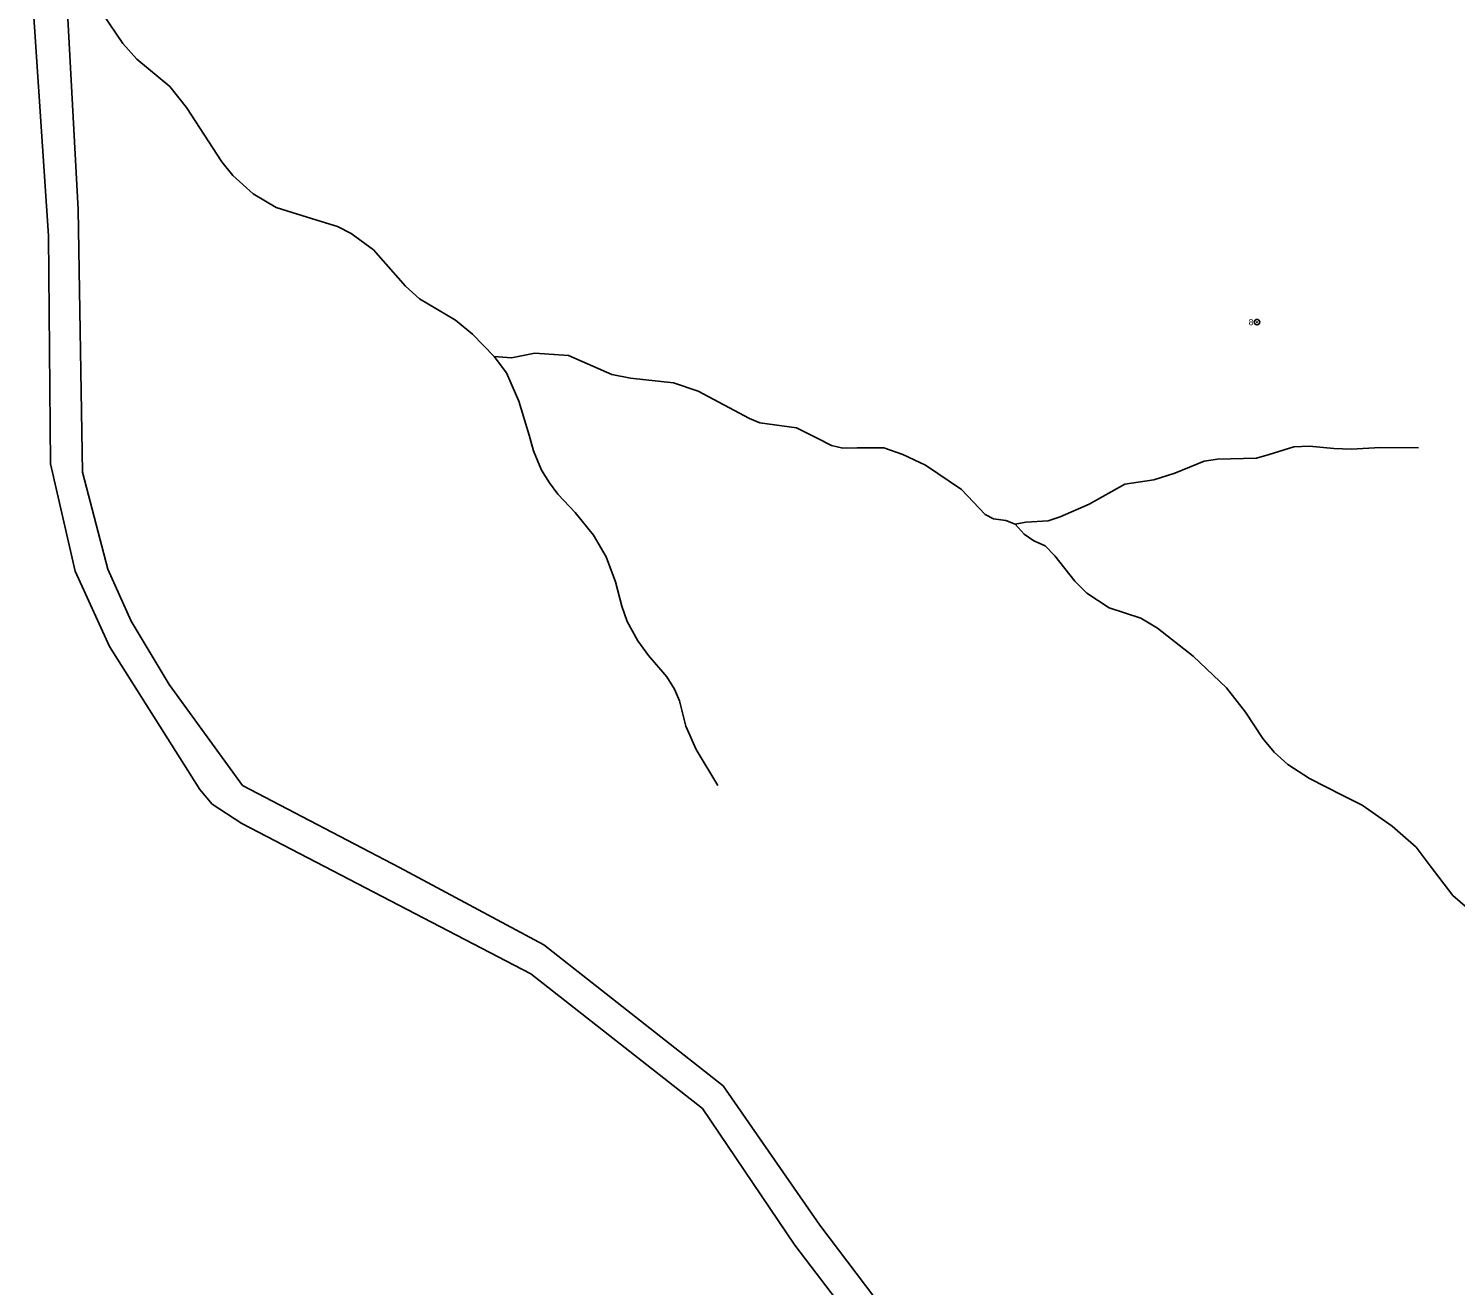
# Model space of a CAD drawing. Extents: x -546762 to -540209, y -1046851 to -1035694.
# Drawn here: x -543936.4 to -543546.4, y -1043117.1 to -1042773.8 of the extents above; entities that cross this region are included whole.
import ezdxf

# ---------------------------------------------------------------- set-up
doc = ezdxf.new("R2010")
doc.units = 0
for name, color, linetype in [('Vrstva 1', 7, 'Continuous'), ('Vrstva 17', 7, 'Continuous'), ('Vrstva 24', 7, 'Continuous'), ('Vrstva 4', 7, 'Continuous')]:
    doc.layers.add(name, color=color, linetype=linetype)

msp = doc.modelspace()

# ---------------------------------------------------------------- linework, layer by layer
at = {"layer": 'Vrstva 1'}
for points in [[(-543930.94, -1042830.38), (-543936.37, -1042748.84)], [(-543922.81, -1042823.23), (-543926.46, -1042755.84)], [(-543921.61, -1042894.96), (-543922.81, -1042823.23)], [(-543930.35, -1042892.69), (-543930.94, -1042830.38)], [(-543923.63, -1042921.97), (-543930.35, -1042892.69)], [(-543914.71, -1042921.46), (-543921.61, -1042894.96)], [(-543908.32, -1042935.68), (-543914.71, -1042921.46)], [(-543914.29, -1042942.58), (-543923.63, -1042921.97)], [(-543897.98, -1042952.93), (-543908.32, -1042935.68)], [(-543889.56, -1042981.62), (-543914.29, -1042942.58)], [(-543877.87, -1042980.57), (-543897.98, -1042952.93)], [(-543886.19, -1042985.65), (-543889.56, -1042981.62)], [(-543834.97, -1043002.95), (-543877.87, -1042980.57)], [(-543878.08, -1042990.91), (-543886.19, -1042985.65)], [(-543799.14, -1043031.96), (-543878.08, -1042990.91)], [(-543795.53, -1043024.03), (-543834.97, -1043002.95)], [(-543746.54, -1043062.55), (-543795.53, -1043024.03)], [(-543752.17, -1043068.79), (-543799.14, -1043031.96)], [(-543720.13, -1043100.6), (-543746.54, -1043062.55)], [(-543726.97, -1043106.1), (-543752.17, -1043068.79)], [(-543695.18, -1043133.63), (-543720.13, -1043100.6)], [(-543699.83, -1043141.7), (-543726.97, -1043106.1)]]:
    msp.add_lwpolyline(points, dxfattribs=at)
at = {"layer": 'Vrstva 24'}
for radius in [0.75, 0.1]:
    msp.add_circle((-543600.66, -1042853.96), radius, dxfattribs=at)
at = {"layer": 'Vrstva 4'}
for points in [[(-543916.14, -1042769.65), (-543910.63, -1042777.9)], [(-543910.63, -1042777.9), (-543906.82, -1042782.14)], [(-543906.82, -1042782.14), (-543897.79, -1042789.63)], [(-543897.79, -1042789.63), (-543893.18, -1042795.32)], [(-543893.18, -1042795.32), (-543883.58, -1042810.14)], [(-543883.58, -1042810.14), (-543880.52, -1042813.96)], [(-543880.52, -1042813.96), (-543875.01, -1042818.96)], [(-543875.01, -1042818.96), (-543868.68, -1042822.66)], [(-543868.68, -1042822.66), (-543858.78, -1042825.72)], [(-543858.78, -1042825.72), (-543851.98, -1042827.81)], [(-543851.98, -1042827.81), (-543848.23, -1042829.72)], [(-543848.23, -1042829.72), (-543842.07, -1042834.22)], [(-543842.07, -1042834.22), (-543833.4, -1042844.15)], [(-543833.4, -1042844.15), (-543829.55, -1042847.61)], [(-543829.55, -1042847.61), (-543819.73, -1042853.41)], [(-543819.73, -1042853.41), (-543815.09, -1042857.26)], [(-543815.09, -1042857.26), (-543809.11, -1042863.35)], [(-543804.43, -1042863.71), (-543798.03, -1042862.48)], [(-543798.03, -1042862.48), (-543788.86, -1042863.09)], [(-543809.11, -1042863.35), (-543804.43, -1042863.71)], [(-543809.11, -1042863.35), (-543805.78, -1042867.86)], [(-543788.86, -1042863.09), (-543777.02, -1042868.31)], [(-543805.78, -1042867.86), (-543802.35, -1042875.55)], [(-543777.02, -1042868.31), (-543771.84, -1042869.31)], [(-543771.84, -1042869.31), (-543760.11, -1042870.57)], [(-543760.11, -1042870.57), (-543753.34, -1042872.84)], [(-543753.34, -1042872.84), (-543739.38, -1042880.33)], [(-543802.35, -1042875.55), (-543799.53, -1042884.83)], [(-543739.38, -1042880.33), (-543736.51, -1042881.45)], [(-543736.51, -1042881.45), (-543726.5, -1042882.85)], [(-543799.53, -1042884.83), (-543798.37, -1042889.14)], [(-543726.5, -1042882.85), (-543721.03, -1042885.55)], [(-543721.03, -1042885.55), (-543716.93, -1042887.67)], [(-543798.37, -1042889.14), (-543796.22, -1042894.45)], [(-543716.93, -1042887.67), (-543713.83, -1042888.43)], [(-543713.83, -1042888.43), (-543709.95, -1042888.32)], [(-543709.95, -1042888.32), (-543702.68, -1042888.29)], [(-543702.68, -1042888.29), (-543697.46, -1042890.13)], [(-543697.46, -1042890.13), (-543691.27, -1042893.04)], [(-543600.79, -1042891.12), (-543597.37, -1042890.15)], [(-543597.37, -1042890.15), (-543590.61, -1042888.06)], [(-543590.61, -1042888.06), (-543586.35, -1042887.81)], [(-543586.35, -1042887.81), (-543579.66, -1042888.53)], [(-543579.66, -1042888.53), (-543574.98, -1042888.67)], [(-543574.98, -1042888.67), (-543566.95, -1042888.21)], [(-543566.95, -1042888.21), (-543556.55, -1042888.31)], [(-543691.27, -1042893.04), (-543681.44, -1042899.7)], [(-543623.1, -1042895.18), (-543615.15, -1042891.91)], [(-543615.15, -1042891.91), (-543611.48, -1042891.41)], [(-543611.48, -1042891.41), (-543600.79, -1042891.12)], [(-543796.22, -1042894.45), (-543794.01, -1042897.88)], [(-543794.01, -1042897.88), (-543791.69, -1042900.92)], [(-543636.82, -1042898.25), (-543628.9, -1042897.02)], [(-543628.9, -1042897.02), (-543623.1, -1042895.18)], [(-543791.69, -1042900.92), (-543786.99, -1042906)], [(-543681.44, -1042899.7), (-543674.92, -1042906.5)], [(-543646.5, -1042903.65), (-543636.82, -1042898.25)], [(-543654.45, -1042907.14), (-543646.5, -1042903.65)], [(-543786.99, -1042906), (-543781.96, -1042912.19)], [(-543674.92, -1042906.5), (-543672.69, -1042907.69)], [(-543672.69, -1042907.69), (-543669.33, -1042908.19)], [(-543669.33, -1042908.19), (-543666.78, -1042909.16)], [(-543666.78, -1042909.16), (-543663.83, -1042908.59)], [(-543666.78, -1042909.16), (-543664.34, -1042911.93)], [(-543663.83, -1042908.59), (-543657.75, -1042908.26)], [(-543657.75, -1042908.26), (-543654.45, -1042907.14)], [(-543781.96, -1042912.19), (-543778.54, -1042918.05)], [(-543664.34, -1042911.93), (-543661.63, -1042913.75)], [(-543661.63, -1042913.75), (-543658.54, -1042915.03)], [(-543658.54, -1042915.03), (-543655.88, -1042917.79)], [(-543778.54, -1042918.05), (-543775.99, -1042924.91)], [(-543655.88, -1042917.79), (-543650.47, -1042924.75)], [(-543775.99, -1042924.91), (-543774.22, -1042931.6)], [(-543650.47, -1042924.75), (-543647.15, -1042927.96)], [(-543647.15, -1042927.96), (-543641.08, -1042931.99)], [(-543774.22, -1042931.6), (-543772.78, -1042935.74)], [(-543641.08, -1042931.99), (-543632.46, -1042934.81)], [(-543772.78, -1042935.74), (-543769.85, -1042941.05)], [(-543632.46, -1042934.81), (-543627.88, -1042937.57)], [(-543769.85, -1042941.05), (-543766.98, -1042945.07)], [(-543627.88, -1042937.57), (-543618.15, -1042945.2)], [(-543766.98, -1042945.07), (-543761.95, -1042950.82)], [(-543618.15, -1042945.2), (-543608.98, -1042953.82)], [(-543761.95, -1042950.82), (-543759.86, -1042954.25)], [(-543759.86, -1042954.25), (-543758.47, -1042957.45)], [(-543608.98, -1042953.82), (-543603.84, -1042960.51)], [(-543758.47, -1042957.45), (-543756.71, -1042964.31)], [(-543603.84, -1042960.51), (-543599.09, -1042967.69)], [(-543756.71, -1042964.31), (-543753.89, -1042970.73)], [(-543599.09, -1042967.69), (-543596, -1042971.39)], [(-543753.89, -1042970.73), (-543747.98, -1042980.52)], [(-543596, -1042971.39), (-543592.24, -1042974.82)], [(-543592.24, -1042974.82), (-543586.33, -1042978.63)], [(-543586.33, -1042978.63), (-543577.43, -1042983.16)], [(-543577.43, -1042983.16), (-543571.96, -1042985.87)], [(-543571.96, -1042985.87), (-543563.72, -1042991.67)], [(-543563.72, -1042991.67), (-543557.15, -1042997.42)], [(-543557.15, -1042997.42), (-543553.34, -1043002.51)], [(-543553.34, -1043002.51), (-543547.2, -1043010.58)], [(-543547.2, -1043010.58), (-543541.79, -1043015.27)]]:
    msp.add_lwpolyline(points, dxfattribs=at)

# ---------------------------------------------------------------- texts
at = {"layer": 'Vrstva 17'}
msp.add_text('8', height=1.7, dxfattribs=at).set_placement((-543602.93, -1042854.81))

doc.saveas('drawing.dxf')
